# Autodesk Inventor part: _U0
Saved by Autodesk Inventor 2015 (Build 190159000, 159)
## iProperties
Created: 2015-06
Part Number: _U0
Material: Generic
Document SubType Name: Modeling
Designer: Franzi-CAD
Density: 1 g/cm^3
Appearance: 191,191,191
Translation Standard: IGES 5.3
FileName: 1 Sistema de RefrigeraÃ§Ã£o Industrial - 3D v3
PreProcessor: AutoCAD 2015 - English
PostProcessor: Build: 160, Release: 2012 RTM - Date: Tue 03/01/2011
Sent Units: millimeter
Uncertainty: 0.01
Author: Franzi-CAD
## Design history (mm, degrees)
node "*U01"
node "1 Sistema de Refrigeração Industrial - 3D v3"
node "Base1"
